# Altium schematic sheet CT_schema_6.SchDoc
size 254 x 245 mm
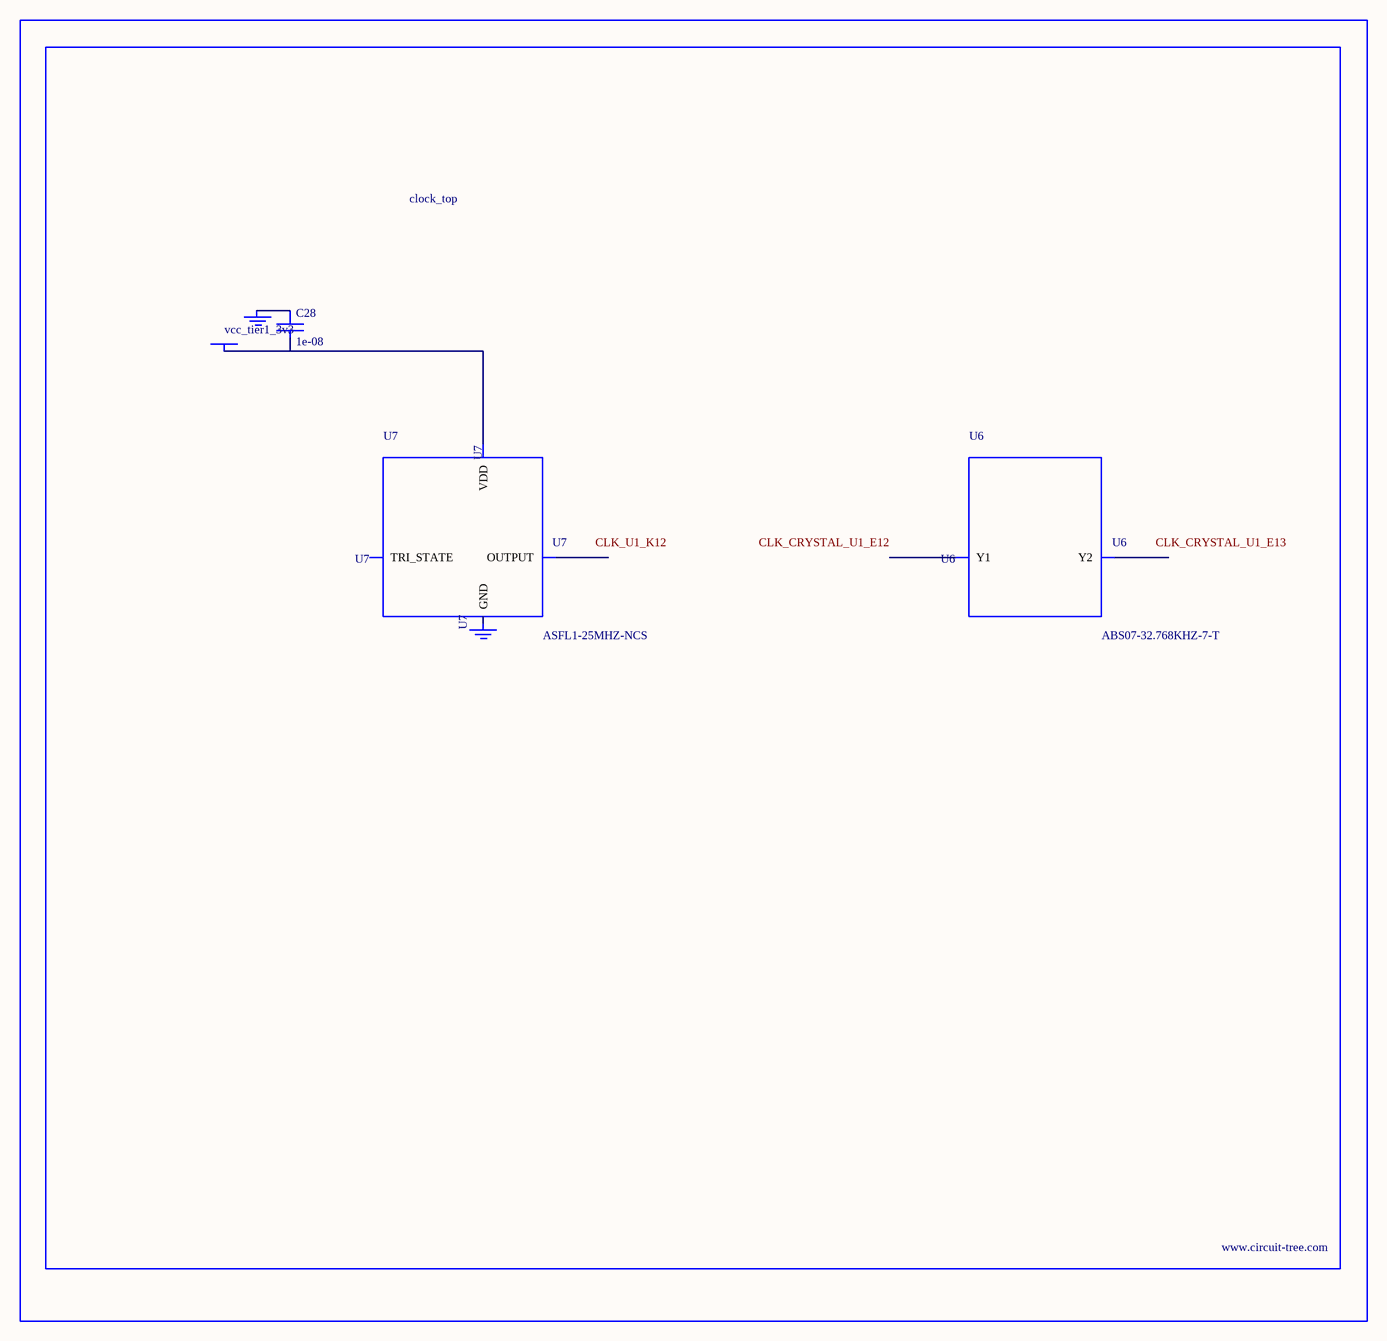
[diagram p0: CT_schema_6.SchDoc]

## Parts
BORDER5  (no value)
C28  1e-08  [C0402]
GND_INSTANCE_5_0  (no value)
GND_INSTANCE_5_1  (no value)
POWER_INSTANCE_5_0  vcc_tier1_3v3
U6  ABS07-32.768KHZ-7-T  [ABS07-32.768KHZ-7-T]
U7  ASFL1-25MHZ-NCS  [ASFL1]

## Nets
NetC28_1: C28.1 GND_INSTANCE_5_0.0(GND)
NetC28_2: C28.2 POWER_INSTANCE_5_0.0(PWR) U7.4(VDD)

Not connected (* = marked no-connect by the designer): GND_INSTANCE_5_1 0(GND); U6 1(Y1) 2(Y2); U7 1(TRI_STATE) 2(GND) 3(OUTPUT)

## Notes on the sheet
- Labels drawn without touching a wire or pin: CLK_CRYSTAL_U1_E12, CLK_CRYSTAL_U1_E13, CLK_U1_K12

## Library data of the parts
BORDER5 = BORDER_PAGE5
C28 = C0402C103K3RAC
GND_INSTANCE_5_0 GND_INSTANCE_5_1 = GND
POWER_INSTANCE_5_0 = PWR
